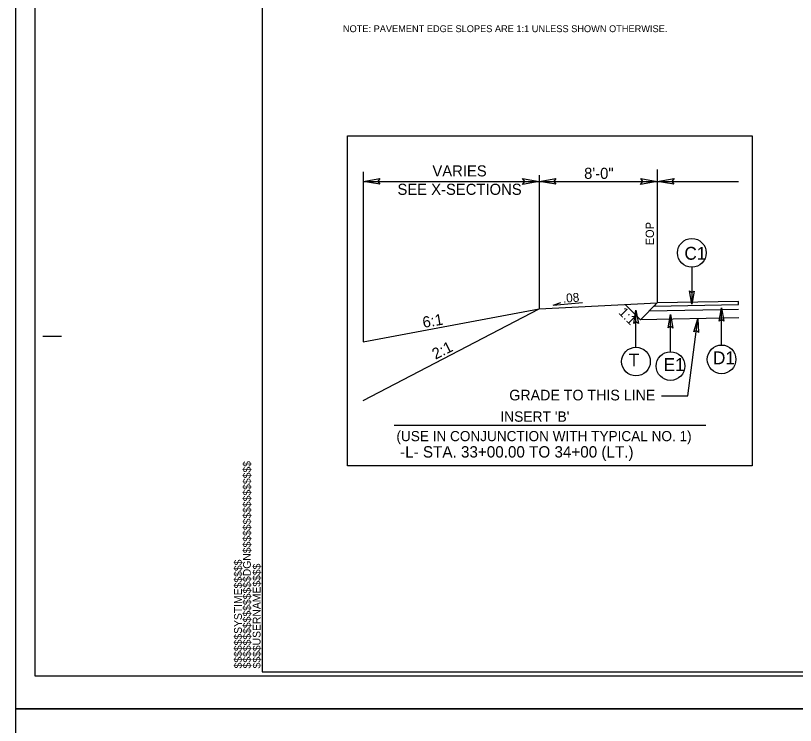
# Model space of a CAD drawing. Extents: x 981824 to 982276, y 44828 to 45204.
# Drawn here: x 982094.36 to 982136.62, y 45089.07 to 45127.55 of the extents above; entities that cross this region are included whole.
import ezdxf

# ---------------------------------------------------------------- set-up
doc = ezdxf.new("R2010")
doc.units = 0
for name, color, linetype in [('Default', 7, 'Continuous'), ('Old_Level_1', 7, 'Continuous'), ('Old_Level_11', 7, 'Continuous'), ('Old_Level_17', 7, 'Continuous'), ('Old_Level_18', 7, 'Continuous'), ('Old_Level_2', 7, 'Continuous'), ('Old_Level_20', 7, 'Continuous'), ('Old_Level_21', 7, 'Continuous'), ('Old_Level_3', 7, 'Continuous'), ('Old_Level_40', 7, 'Continuous'), ('Old_Level_41', 7, 'Continuous'), ('Old_Level_50', 7, 'Continuous'), ('Old_Level_51', 7, 'Continuous'), ('Old_Level_52', 7, 'Continuous'), ('Prop Dimension Text', 7, 'Continuous'), ('Typical Terminator CELL', 7, 'Continuous')]:
    doc.layers.add(name, color=color, linetype=linetype)

msp = doc.modelspace()

# ---------------------------------------------------------------- linework, layer by layer
at = {"layer": 'Old_Level_1'}
for p, q in [((982113.203, 45119.075), (982113.203, 45109.868)), ((982129.141, 45119.206), (982129.141, 45111.97)), ((982122.741, 45118.901), (982122.741, 45111.647)), ((982113.203, 45118.559), (982122.741, 45118.559)), ((982122.741, 45118.559), (982129.141, 45118.559)), ((982129.141, 45118.559), (982133.548, 45118.559)), ((982122.741, 45111.647), (982129.141, 45111.97)), ((982123.49, 45111.846), (982125.087, 45111.988)), ((982123.49, 45111.846), (982123.912, 45111.988)), ((982127.401, 45111.882), (982128.224, 45111.059)), ((982129.141, 45111.97), (982128.224, 45111.058)), ((982133.548, 45112.058), (982129.141, 45111.97)), ((982113.203, 45106.689), (982122.741, 45111.647)), ((982113.203, 45109.868), (982122.741, 45111.647)), ((982133.548, 45111.625), (982128.692, 45111.523)), ((982133.557, 45111.166), (982128.224, 45111.059)), ((982130.798, 45106.94), (982131.335, 45111.103)), ((982129.372, 45106.94), (982130.798, 45106.94))]:
    msp.add_line(p, q, dxfattribs=at)
at = {"layer": 'Old_Level_11'}
for points in [[(982131.135, 45112.618), (982131.011, 45111.898), (982130.883, 45112.622), (982131.011, 45112.53)], [(982127.861, 45110.862), (982127.985, 45111.582), (982128.113, 45110.858), (982127.985, 45110.95)], [(982132.5, 45110.98), (982132.624, 45111.7), (982132.752, 45110.976), (982132.624, 45111.068)], [(982129.733, 45110.617), (982129.857, 45111.337), (982129.985, 45110.613), (982129.857, 45110.705)]]:
    msp.add_lwpolyline(points, close=True, dxfattribs=at)
at = {"layer": 'Old_Level_17'}
msp.add_lwpolyline([(982112.343, 45121.024), (982134.284, 45121.024), (982134.284, 45103.14), (982112.343, 45103.14)], close=True, dxfattribs=at)
at = {"layer": 'Old_Level_18'}
msp.add_line((982107.72, 45091.969), (982107.72, 45091.969), dxfattribs=at)
msp.add_line((982107.72, 45091.969), (982107.72, 45091.969), dxfattribs=at)
msp.add_line((982107.72, 45091.969), (982107.72, 45091.969), dxfattribs=at)
msp.add_lwpolyline([(982227.72, 45175.969), (982107.72, 45175.969), (982107.72, 45091.969), (982227.72, 45091.969)], close=True, dxfattribs=at)
at = {"layer": 'Old_Level_21'}
msp.add_line((982133.548, 45111.886), (982133.548, 45112.058), dxfattribs=at)
msp.add_lwpolyline([(982133.548, 45112.058), (982129.141, 45111.97), (982128.965, 45111.795), (982133.548, 45111.886)], dxfattribs=at)
at = {"layer": 'Old_Level_3'}
msp.add_line((982131.77, 45105.328), (982114.87, 45105.328), dxfattribs=at)
at = {"layer": 'Old_Level_40'}
msp.add_line((982107.72, 45091.969), (982107.72, 45091.969), dxfattribs=at)
msp.add_line((982107.72, 45091.969), (982107.72, 45091.969), dxfattribs=at)
msp.add_line((982107.72, 45091.969), (982107.72, 45091.969), dxfattribs=at)
msp.add_line((982107.72, 45091.969), (982107.72, 45091.969), dxfattribs=at)
msp.add_line((982107.72, 45091.969), (982107.72, 45091.969), dxfattribs=at)
msp.add_line((982107.72, 45091.969), (982107.72, 45091.969), dxfattribs=at)
at = {"layer": 'Old_Level_41'}
msp.add_line((982095.84, 45110.169), (982096.84, 45110.169), dxfattribs=at)
msp.add_lwpolyline([(982110.72, 45091.969), (982110.72, 45091.969)], dxfattribs=at)
msp.add_lwpolyline([(982110.72, 45091.969), (982110.72, 45091.969)], dxfattribs=at)
at = {"layer": 'Old_Level_50'}
msp.add_line((982094.36, 45089.969), (982094.36, 45089.969), dxfattribs=at)
msp.add_lwpolyline([(982228.72, 45176.173), (982095.4, 45176.173), (982095.4, 45091.765), (982228.72, 45091.765)], close=True, dxfattribs=at)
at = {"layer": 'Old_Level_51'}
for points in [[(982229.08, 45177.969), (982094.36, 45177.969), (982094.36, 45089.969), (982229.08, 45089.969)], [(982229.08, 45089.969), (982094.36, 45089.969), (982094.36, 45001.969), (982229.08, 45001.969)]]:
    msp.add_lwpolyline(points, close=True, dxfattribs=at)
at = {"layer": 'Old_Level_52'}
msp.add_line((982095.4, 45091.765), (982095.4, 45091.765), dxfattribs=at)
at = {"layer": 'Prop Dimension Text'}
for p, q in [((982131.011, 45113.908), (982131.011, 45111.898)), ((982127.985, 45109.572), (982127.985, 45111.582)), ((982132.624, 45109.691), (982132.624, 45111.7)), ((982129.857, 45109.327), (982129.857, 45111.337))]:
    msp.add_line(p, q, dxfattribs=at)
for centre in [(982131.011, 45114.685), (982127.983, 45108.794), (982129.857, 45108.55), (982132.623, 45108.912)]:
    msp.add_circle(centre, 0.778, dxfattribs=at)
at = {"layer": 'Typical Terminator CELL'}
for points in [[(982114.103, 45118.404), (982113.203, 45118.559), (982114.108, 45118.719), (982113.993, 45118.559)], [(982121.841, 45118.714), (982122.741, 45118.559), (982121.836, 45118.399), (982121.951, 45118.559)], [(982123.641, 45118.404), (982122.741, 45118.559), (982123.646, 45118.719), (982123.531, 45118.559)], [(982128.241, 45118.714), (982129.141, 45118.559), (982128.236, 45118.399), (982128.351, 45118.559)], [(982130.041, 45118.404), (982129.141, 45118.559), (982130.046, 45118.719), (982129.931, 45118.559)], [(982131.122, 45110.404), (982131.335, 45111.103), (982131.371, 45110.368), (982131.256, 45110.476)]]:
    msp.add_lwpolyline(points, close=True, dxfattribs=at)

# ---------------------------------------------------------------- texts
at = {"layer": 'Default'}
msp.add_text('NOTE: PAVEMENT EDGE SLOPES ARE 1:1 UNLESS SHOWN OTHERWISE.', height=0.37327, dxfattribs=at).set_placement((982112.101, 45126.65))
at = {"layer": 'Old_Level_1'}
for s, p in [('VARIES', (982116.95, 45118.831)), ('8\'-0"', (982125.174, 45118.698)), ('SEE X-SECTIONS', (982115.056, 45117.831))]:
    msp.add_text(s, height=0.6, dxfattribs=at).set_placement(p)
for s, height, rotation, p in [('EOP', 0.4485, 90, (982128.956, 45115.092)), ('6:1', 0.6, 9.4617, (982116.466, 45110.618)), ('2:1', 0.6, 26.5646, (982117.115, 45108.892))]:
    msp.add_text(s, height=height, rotation=rotation, dxfattribs=at).set_placement(p)
at = {"layer": 'Old_Level_2'}
msp.add_text('.08', height=0.48, rotation=4.5739, dxfattribs=at).set_placement((982124.039, 45111.976))
at = {"layer": 'Old_Level_20'}
for s, p in [('C1', (982130.609, 45114.315)), ('D1', (982132.157, 45108.648)), ('T ', (982127.592, 45108.529)), ('E1', (982129.484, 45108.285))]:
    msp.add_text(s, height=0.696, dxfattribs=at).set_placement(p)
at = {"layer": 'Old_Level_3'}
msp.add_text('1:1', height=0.5233, rotation=315, dxfattribs=at).set_placement((982127.001, 45111.42))
for s, height, p in [('GRADE TO THIS LINE', 0.576, (982121.118, 45106.689)), ("INSERT 'B'", 0.5606, (982120.629, 45105.531)), ('(USE IN CONJUNCTION WITH TYPICAL NO. 1)', 0.55074, (982115.001, 45104.478)), ('-L- STA. 33+00.00 TO 34+00 (LT.)', 0.61669, (982115.2, 45103.591))]:
    msp.add_text(s, height=height, dxfattribs=at).set_placement(p)
at = {"layer": 'Old_Level_41'}
for s, p in [('$$$$$$$$$$$$$$$$DGN$$$$$$$$$$$$$$$$', (982107.108, 45092.158)), ('$$$$$$SYSTIME$$$$$', (982106.624, 45092.158)), ('$$$$USERNAME$$$$', (982107.634, 45092.159))]:
    msp.add_text(s, height=0.42, rotation=90, dxfattribs=at).set_placement(p)

doc.saveas('drawing.dxf')
